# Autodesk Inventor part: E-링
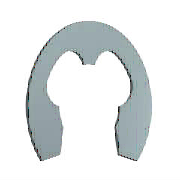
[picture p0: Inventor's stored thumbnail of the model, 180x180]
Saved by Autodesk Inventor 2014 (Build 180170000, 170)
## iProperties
IsCustomPart: 1
Created: 2012-02
Part Number: E-링
Material: 강철, 연강
Description: 일반용 테이퍼 및 줄어든 횡단면 리테이닝 링 - E-링 외부 시리즈 3CM1 리테이닝 링
Document SubType Name: Modeling
Standard: ANSI B27.7
Designer: mduedu
Standard Revision: 1999
Standards Organization: ANSI
Language: ko-KR
Size Designation: 6
Categories: <MemberInstance><Categories><Category DisplayName="샤프트 부품" InternalName="7f7aeb1f-a693-4053-b835-cee3144e0d98" Mnemonic="SHFT"><Category DisplayName="써클립" Inter
Density: 1 g/cm^3
Appearance: Blue - Wall Paint - Glossy
Author: mduedu
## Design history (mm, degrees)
sketch "스케치1"
  geometry: L1 (-0.485, 0.024)-(0, 0.024) reference; L2 (-3.206, 0)-(3.486, 0) reference; L3 (-2.223, -3.946)-(2.223, -3.946); L4 (0, 1.949)-(0, -3.479) reference; L5 (-2.91, -2.006)-(-2.435, -2.006); L6 (-0.485, -0.066)-(-0.485, 0.405); L7 (0, 2.574)-(2.53, 2.574); L8 (-2.223, -3.946)-(-3.022, -6.291); L9 (0, -0.551)-(-1.278, -0.551); L10 (2.223, -3.946)-(3.022, -6.291); L11 (2.91, -2.006)-(2.435, -2.006); L12 (0.485, -0.066)-(0.485, 0.405); C1 r 3 at (0, -2.976); A1 r 2.425 centre (0, -2.976) between (-2.297, -2.199) and (-2.223, -3.946); A2 r 0.485 centre (0, -0.066) between (-0.485, -0.066) and (0.485, -0.066); A3 r 5.55 centre (0, -2.976) between (4.27, -6.521) and (-4.27, -6.521); A4 r 3.88 centre (0, -2.976) between (-0.97, 0.78) and (-3.424, -1.15); A5 r 0.388 centre (-0.873, 0.405) between (-0.485, 0.405) and (-0.97, 0.78); A6 r 0.582 centre (-2.91, -1.424) between (-3.424, -1.15) and (-2.91, -2.006); A7 r 0.145 centre (-2.435, -2.152) between (-2.297, -2.199) and (-2.435, -2.006); A8 r 0.727 centre (-3.711, -6.057) between (-4.27, -6.521) and (-3.022, -6.291); A9 r 0.727 centre (3.711, -6.057) between (3.022, -6.291) and (4.27, -6.521); A10 r 2.425 centre (0, -2.976) between (2.223, -3.946) and (2.297, -2.199); A11 r 0.145 centre (2.435, -2.152) between (2.435, -2.006) and (2.297, -2.199); A12 r 0.582 centre (2.91, -1.424) between (2.91, -2.006) and (3.424, -1.15); A13 r 3.88 centre (0, -2.976) between (3.424, -1.15) and (0.97, 0.78); A14 r 0.388 centre (0.873, 0.405) between (0.97, 0.78) and (0.485, 0.405); 1 further point
  constraints: 30 point on circle, 20 end point, 15 centre point, 13 symmetric about line, 12 tangent, 8 point on line, 4 parallel, 2 coincident, 2 horizontal, 1 concentric, 1 perpendicular, 1 vertical alignment, 9 other
  dimensions: "d0" = 6 diameter of C1 (= WD); "d3" = 0.97 distance from line of A1.centre L3 (= 0.2 x ND); "d4" = 0.485 radius of A2 (= 0.1 x ND); "d5" = 11.1 diameter of A3 (= SD2); "d8" = 3.88 radius of A4 (= 0.8 x ND); "d9" = 0.97 distance from line of A1.centre L5 (= 0.2 x ND); "d10" = 0.388 radius of A5 (= 0.08 x ND); "d11" = 0.582 radius of A6 (= 0.12 x ND); "d12" = 0.1455 radius of A7 (= 0.03 x ND); "d13" = 0.7275 radius of A8 (= 0.15 x ND); "d14" = 2.425 distance from line of A1.centre L9 (= 0.5 x ND); "d15" = 2.425 radius of A1 (= 0.5 x ND)
extrude "본체" new body sketch "스케치1" distance "d16" = 0.6 (= SD); taper "d17" = 0 deg
workaxis "Work Axis1"
workaxis "Work Axis2"
workplane "Work Plane1"
workplane "Work Plane2"
body "Solid1"
other parameters: "ND" = 4.85 [user parameter; used in 14 equation terms], "SD" = 0.6 [user parameter; used in 1 equation term], "WD" = 6 (= WDMIN) [user parameter; used in 1 equation term], "d1" = 7.76 (= 1.6 x ND), "d2" = 4.85 (= ND), "SD2" = 11.1 [user parameter; used in 1 equation term], "d6" = 4.85 (= ND), "d7" = 0.7275 (= 0.15 x ND), "d18" = 0, "d19" = 0, "d27" = 0, "d28" = 0, "WDMIN" = 6 [user parameter; used in 1 equation term], "SNB" = 0.7 [user parameter], "WDMAX" = 7 [user parameter], "BUBRMI" = 1.2 [user parameter]
